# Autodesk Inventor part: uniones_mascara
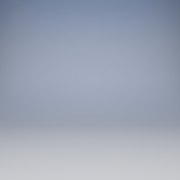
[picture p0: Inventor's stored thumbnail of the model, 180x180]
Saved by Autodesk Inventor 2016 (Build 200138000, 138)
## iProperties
Created: 2017-06
Part Number: uniones_mascara
Material: Generic
Document SubType Name: Modeling
Designer: laboratorioesan
Density: 1 g/cm^3
Appearance: Default
Author: laboratorioesan
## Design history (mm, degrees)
